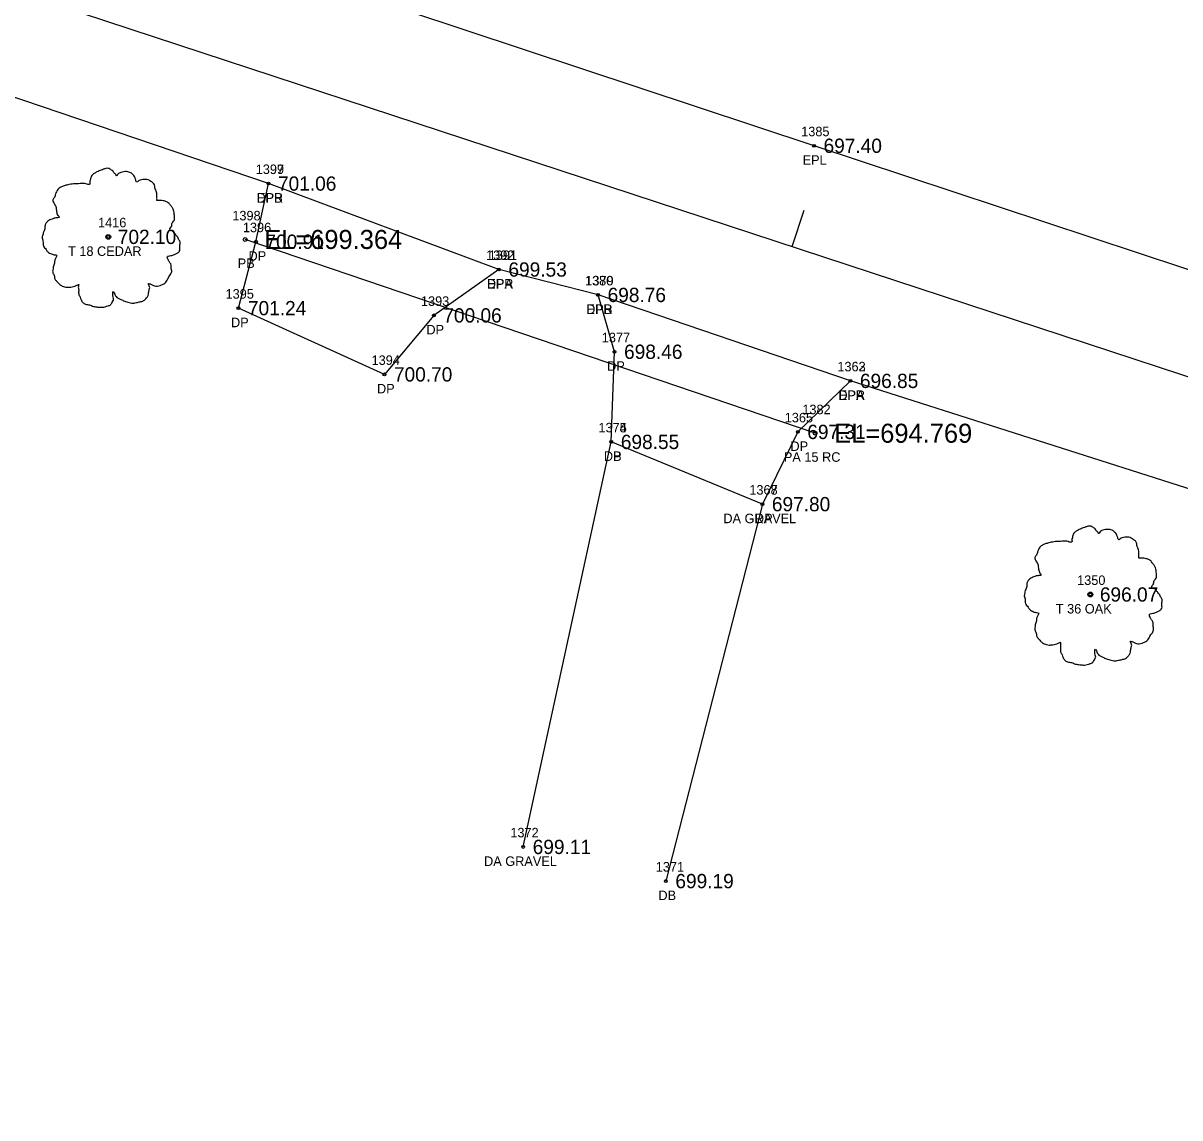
# Model space of a CAD drawing. Extents: x 1655137 to 1657928, y 1003994 to 1005407.
# Drawn here: x 1655718.8 to 1655840.3, y 1004724 to 1004839 of the extents above; entities that cross this region are included whole.
import ezdxf

# ---------------------------------------------------------------- set-up
doc = ezdxf.new("R2010")
doc.units = 0
for name, color, linetype in [('RD_EX_DR_Pipe', 7, 'Continuous'), ('RD_EX_DR_Pipe_txCode', 7, 'Continuous'), ('RD_EX_Driveway', 7, 'Continuous'), ('RD_EX_Driveway_txCode', 7, 'Continuous'), ('RD_EX_Road', 7, 'Continuous'), ('RD_EX_Road_txCode', 7, 'Continuous'), ('RD_EX_TX_Driveway_ELEV', 7, 'Continuous'), ('RD_EX_TX_Road_ELEV', 7, 'Continuous'), ('RD_EX_TX_VEG_ELEV', 7, 'Continuous'), ('RD_EX_VEG', 7, 'Continuous'), ('RD_EX_VEG_txCode', 7, 'Continuous'), ('RD_HC_Cl', 7, 'Continuous'), ('RD_HC_Data_Tic', 7, 'Continuous'), ('RD_SMD_Locator', 7, 'Continuous'), ('RD_TX_Pipe_ElevEX', 7, 'Continuous')]:
    doc.layers.add(name, color=color, linetype=linetype)

msp = doc.modelspace()

# ---------------------------------------------------------------- linework, layer by layer
at = {"layer": 'RD_EX_DR_Pipe'}
msp.add_line((1655802.03, 1004795.9), (1655742.14, 1004816.26), dxfattribs=at)
at = {"layer": 'RD_EX_Driveway'}
for p, q in [((1655771.35, 1004752.44), (1655780.61, 1004794.99)), ((1655796.48, 1004788.45), (1655786.34, 1004748.85))]:
    msp.add_line(p, q, dxfattribs=at)
for points in [[(1655768.8, 1004813.1), (1655761.96, 1004808.28), (1655756.77, 1004802.08), (1655741.43, 1004809.04), (1655743.27, 1004816.02), (1655744.59, 1004822.13)], [(1655805.73, 1004801.4), (1655800.2, 1004796.04), (1655796.48, 1004788.45), (1655780.61, 1004794.99), (1655780.95, 1004804.46), (1655779.22, 1004810.43)]]:
    msp.add_lwpolyline(points, dxfattribs=at)
at = {"layer": 'RD_EX_Road'}
for points in [[(1656365.12, 1004639.99), (1656336.04, 1004649.34), (1656302.55, 1004660.37), (1656279.15, 1004668.23), (1656240.07, 1004681.05), (1656188.23, 1004698.03), (1656166.72, 1004705.51), (1656141.16, 1004714.06), (1656093.11, 1004730.11), (1656044.16, 1004746.75), (1655996.36, 1004762.45), (1655947.2, 1004778.68), (1655899.09, 1004794.03), (1655850.62, 1004809.99), (1655801.91, 1004826.1), (1655753.09, 1004842.31), (1655704.25, 1004858.1)], [(1656358.5, 1004619.83), (1656328.78, 1004629.48), (1656280.77, 1004645.39), (1656247.66, 1004656.11), (1656244.5, 1004656.52), (1656222.03, 1004663.57), (1656217.65, 1004665.96), (1656183.42, 1004677.32), (1656134.59, 1004693.72), (1656086.19, 1004709.75), (1656037.58, 1004726.13), (1655989.57, 1004741.99), (1655940.62, 1004757.88), (1655892.37, 1004773.61), (1655843.48, 1004789.36), (1655805.73, 1004801.4), (1655779.22, 1004810.43), (1655768.8, 1004813.1), (1655744.59, 1004822.13), (1655698.83, 1004837.65)]]:
    msp.add_lwpolyline(points, dxfattribs=at)
at = {"layer": 'RD_EX_VEG'}
for centre, radius in [((1655727.76, 1004816.53), 0.25), ((1655727.75, 1004816.52), 0.0001), ((1655830.94, 1004778.96), 0.25), ((1655830.93, 1004778.94), 0.0001)]:
    msp.add_circle(centre, radius, dxfattribs=at)
for points in [[(1655727.89, 1004823.7), (1655727.59, 1004823.73), (1655727.27, 1004823.63), (1655727.02, 1004823.53), (1655726.79, 1004823.45), (1655726.57, 1004823.35), (1655726.27, 1004823.18), (1655726.04, 1004822.98), (1655725.92, 1004822.73), (1655725.87, 1004822.5), (1655725.82, 1004822.23), (1655725.82, 1004822.05), (1655725.69, 1004822.03), (1655725.54, 1004822.05), (1655725.29, 1004822.13), (1655725.04, 1004822.13), (1655724.8, 1004822.13), (1655724.45, 1004822.1), (1655724.1, 1004822.1), (1655723.82, 1004822.05), (1655723.5, 1004822), (1655723.12, 1004821.88), (1655722.77, 1004821.75), (1655722.47, 1004821.5), (1655722.22, 1004821.03), (1655722.1, 1004820.68), (1655721.95, 1004820.43), (1655722.1, 1004819.98), (1655722.27, 1004819.63), (1655722.3, 1004819.43), (1655722.37, 1004819), (1655722.47, 1004818.78), (1655722.6, 1004818.58), (1655722.52, 1004818.55), (1655722.15, 1004818.5), (1655721.85, 1004818.4), (1655721.42, 1004818.18), (1655721.2, 1004817.95), (1655721.1, 1004817.63), (1655721.07, 1004817.28), (1655720.97, 1004817.08), (1655720.9, 1004816.8), (1655720.87, 1004816.73), (1655720.82, 1004816.4), (1655720.92, 1004815.95), (1655720.95, 1004815.6), (1655721.07, 1004815.38), (1655721.22, 1004815.2), (1655721.4, 1004814.95), (1655721.8, 1004814.73), (1655722.12, 1004814.63), (1655722.32, 1004814.61), (1655722.15, 1004814.11), (1655722.1, 1004813.76), (1655721.97, 1004813.36), (1655721.97, 1004813.28), (1655721.92, 1004812.81), (1655722.07, 1004812.48), (1655722.15, 1004812.11), (1655722.32, 1004811.88), (1655722.6, 1004811.58), (1655722.92, 1004811.36), (1655723.42, 1004811.23), (1655723.82, 1004811.26), (1655724.4, 1004811.43), (1655724.65, 1004811.51), (1655724.62, 1004811.33), (1655724.65, 1004810.96), (1655724.65, 1004810.53), (1655724.8, 1004810.21), (1655724.9, 1004809.93), (1655725.04, 1004809.68), (1655725.37, 1004809.46), (1655725.77, 1004809.38), (1655726.19, 1004809.23), (1655726.64, 1004809.16), (1655727.14, 1004809.13), (1655727.74, 1004809.28), (1655728.02, 1004809.41), (1655728.12, 1004809.58), (1655728.32, 1004809.96), (1655728.27, 1004810.18), (1655728.29, 1004810.78), (1655728.39, 1004810.61), (1655728.57, 1004810.26), (1655729.07, 1004809.96), (1655729.47, 1004809.78), (1655729.94, 1004809.63), (1655730.24, 1004809.56), (1655730.72, 1004809.63), (1655731.09, 1004809.71), (1655731.47, 1004809.83), (1655731.77, 1004810.11), (1655731.94, 1004810.38), (1655731.99, 1004810.66), (1655732.07, 1004811.03), (1655732.12, 1004811.21)], [(1655732.12, 1004811.21), (1655732.04, 1004811.38), (1655731.99, 1004811.63), (1655732.07, 1004811.61), (1655732.24, 1004811.56), (1655732.52, 1004811.43), (1655732.74, 1004811.36), (1655733.07, 1004811.38), (1655733.34, 1004811.48), (1655733.79, 1004811.76), (1655734.07, 1004812.23), (1655734.34, 1004812.63), (1655734.42, 1004812.96), (1655734.37, 1004813.18), (1655734.34, 1004813.68), (1655734.14, 1004813.93), (1655734.09, 1004814.06), (1655733.99, 1004814.46), (1655734.07, 1004814.51), (1655734.34, 1004814.56), (1655734.72, 1004814.68), (1655734.99, 1004814.8), (1655735.22, 1004814.98), (1655735.29, 1004815.2), (1655735.27, 1004815.6), (1655735.32, 1004816), (1655735.24, 1004816.15), (1655735.14, 1004816.3), (1655735.07, 1004816.5), (1655734.92, 1004816.65), (1655734.82, 1004816.8), (1655734.72, 1004816.9), (1655734.59, 1004817.05), (1655734.42, 1004817.18), (1655734.27, 1004817.23), (1655734.22, 1004817.38), (1655734.37, 1004817.58), (1655734.42, 1004817.68), (1655734.44, 1004817.9), (1655734.67, 1004818.25), (1655734.72, 1004818.65), (1655734.67, 1004819.08), (1655734.62, 1004819.35), (1655734.47, 1004819.63), (1655734.27, 1004819.88), (1655734.14, 1004820.05), (1655733.97, 1004820.18), (1655733.64, 1004820.3), (1655733.39, 1004820.35), (1655733.04, 1004820.35), (1655732.84, 1004820.4), (1655732.87, 1004820.45), (1655732.87, 1004820.6), (1655732.87, 1004820.88), (1655732.79, 1004821.33), (1655732.64, 1004821.83), (1655732.64, 1004821.85), (1655732.54, 1004822.1), (1655732.32, 1004822.3), (1655732.14, 1004822.4), (1655731.94, 1004822.53), (1655731.69, 1004822.55), (1655731.39, 1004822.55), (1655731.12, 1004822.5), (1655730.92, 1004822.4), (1655730.74, 1004822.28), (1655730.67, 1004822.43), (1655730.57, 1004822.73), (1655730.52, 1004822.88), (1655730.37, 1004823.05), (1655730.14, 1004823.25), (1655729.69, 1004823.38), (1655729.07, 1004823.3), (1655728.77, 1004823.1), (1655728.62, 1004822.93), (1655728.57, 1004823.05), (1655728.37, 1004823.25), (1655728.27, 1004823.43), (1655728.09, 1004823.55), (1655727.94, 1004823.65), (1655727.84, 1004823.7)], [(1655831.07, 1004786.12), (1655830.77, 1004786.15), (1655830.45, 1004786.05), (1655830.2, 1004785.95), (1655829.97, 1004785.87), (1655829.75, 1004785.77), (1655829.45, 1004785.6), (1655829.22, 1004785.4), (1655829.1, 1004785.15), (1655829.05, 1004784.92), (1655829, 1004784.65), (1655829, 1004784.47), (1655828.87, 1004784.45), (1655828.72, 1004784.47), (1655828.47, 1004784.55), (1655828.22, 1004784.55), (1655827.97, 1004784.55), (1655827.62, 1004784.52), (1655827.27, 1004784.52), (1655827, 1004784.47), (1655826.67, 1004784.42), (1655826.3, 1004784.3), (1655825.95, 1004784.17), (1655825.65, 1004783.92), (1655825.4, 1004783.45), (1655825.27, 1004783.1), (1655825.12, 1004782.85), (1655825.27, 1004782.4), (1655825.45, 1004782.05), (1655825.47, 1004781.85), (1655825.55, 1004781.42), (1655825.65, 1004781.2), (1655825.77, 1004781), (1655825.7, 1004780.97), (1655825.32, 1004780.92), (1655825.02, 1004780.82), (1655824.6, 1004780.6), (1655824.37, 1004780.37), (1655824.27, 1004780.05), (1655824.25, 1004779.7), (1655824.15, 1004779.5), (1655824.07, 1004779.23), (1655824.05, 1004779.15), (1655824, 1004778.83), (1655824.1, 1004778.38), (1655824.12, 1004778.03), (1655824.25, 1004777.8), (1655824.4, 1004777.63), (1655824.57, 1004777.38), (1655824.97, 1004777.15), (1655825.3, 1004777.05), (1655825.5, 1004777.03), (1655825.32, 1004776.53), (1655825.27, 1004776.18), (1655825.15, 1004775.78), (1655825.15, 1004775.7), (1655825.1, 1004775.23), (1655825.25, 1004774.9), (1655825.32, 1004774.53), (1655825.5, 1004774.3), (1655825.77, 1004774), (1655826.1, 1004773.78), (1655826.6, 1004773.65), (1655827, 1004773.68), (1655827.57, 1004773.85), (1655827.82, 1004773.93), (1655827.8, 1004773.75), (1655827.82, 1004773.38), (1655827.82, 1004772.95), (1655827.97, 1004772.63), (1655828.07, 1004772.35), (1655828.22, 1004772.1), (1655828.55, 1004771.88), (1655828.95, 1004771.8), (1655829.37, 1004771.65), (1655829.82, 1004771.58), (1655830.32, 1004771.55), (1655830.92, 1004771.7), (1655831.2, 1004771.83), (1655831.3, 1004772), (1655831.5, 1004772.38), (1655831.45, 1004772.6), (1655831.47, 1004773.2), (1655831.57, 1004773.03), (1655831.75, 1004772.68), (1655832.24, 1004772.38), (1655832.64, 1004772.2), (1655833.12, 1004772.05), (1655833.42, 1004771.98), (1655833.89, 1004772.05), (1655834.27, 1004772.13), (1655834.64, 1004772.25), (1655834.94, 1004772.53), (1655835.12, 1004772.8), (1655835.17, 1004773.08), (1655835.24, 1004773.45), (1655835.29, 1004773.63)], [(1655835.29, 1004773.63), (1655835.22, 1004773.8), (1655835.17, 1004774.05), (1655835.24, 1004774.03), (1655835.42, 1004773.98), (1655835.69, 1004773.85), (1655835.92, 1004773.78), (1655836.24, 1004773.8), (1655836.52, 1004773.9), (1655836.97, 1004774.18), (1655837.24, 1004774.65), (1655837.52, 1004775.05), (1655837.59, 1004775.38), (1655837.54, 1004775.6), (1655837.52, 1004776.1), (1655837.32, 1004776.35), (1655837.27, 1004776.48), (1655837.17, 1004776.88), (1655837.24, 1004776.93), (1655837.52, 1004776.98), (1655837.89, 1004777.1), (1655838.17, 1004777.23), (1655838.39, 1004777.4), (1655838.47, 1004777.63), (1655838.44, 1004778.03), (1655838.49, 1004778.43), (1655838.42, 1004778.58), (1655838.32, 1004778.73), (1655838.24, 1004778.93), (1655838.09, 1004779.08), (1655837.99, 1004779.23), (1655837.89, 1004779.33), (1655837.77, 1004779.48), (1655837.59, 1004779.6), (1655837.44, 1004779.65), (1655837.39, 1004779.8), (1655837.54, 1004780), (1655837.59, 1004780.1), (1655837.62, 1004780.32), (1655837.84, 1004780.67), (1655837.89, 1004781.07), (1655837.84, 1004781.5), (1655837.79, 1004781.77), (1655837.64, 1004782.05), (1655837.44, 1004782.3), (1655837.32, 1004782.47), (1655837.14, 1004782.6), (1655836.82, 1004782.72), (1655836.57, 1004782.77), (1655836.22, 1004782.77), (1655836.02, 1004782.82), (1655836.04, 1004782.87), (1655836.04, 1004783.02), (1655836.04, 1004783.3), (1655835.97, 1004783.75), (1655835.82, 1004784.25), (1655835.82, 1004784.27), (1655835.72, 1004784.52), (1655835.49, 1004784.72), (1655835.32, 1004784.82), (1655835.12, 1004784.95), (1655834.87, 1004784.97), (1655834.57, 1004784.97), (1655834.29, 1004784.92), (1655834.09, 1004784.82), (1655833.92, 1004784.7), (1655833.84, 1004784.85), (1655833.74, 1004785.15), (1655833.69, 1004785.3), (1655833.54, 1004785.47), (1655833.32, 1004785.67), (1655832.87, 1004785.8), (1655832.24, 1004785.72), (1655831.94, 1004785.52), (1655831.79, 1004785.35), (1655831.75, 1004785.47), (1655831.55, 1004785.67), (1655831.45, 1004785.85), (1655831.27, 1004785.97), (1655831.12, 1004786.07), (1655831.02, 1004786.12)]]:
    msp.add_spline(points, degree=3, dxfattribs=at)
at = {"layer": 'RD_HC_Cl'}
msp.add_line((1655701.51, 1004847.78), (1656069.26, 1004726.84), dxfattribs=at)
at = {"layer": 'RD_HC_Data_Tic'}
msp.add_line((1655799.61, 1004815.52), (1655800.86, 1004819.32), dxfattribs=at)
at = {"layer": 'RD_SMD_Locator'}
for centre, radius in [((1655801.91, 1004826.1), 0.15), ((1655744.59, 1004822.13), 0.15), ((1655744.59, 1004822.13), 0.15), ((1655727.76, 1004816.53), 0.15), ((1655742.14, 1004816.26), 0.2), ((1655743.27, 1004816.02), 0.15), ((1655768.8, 1004813.1), 0.15), ((1655768.8, 1004813.1), 0.15), ((1655779.22, 1004810.43), 0.15), ((1655779.22, 1004810.43), 0.15), ((1655741.43, 1004809.04), 0.15), ((1655761.96, 1004808.28), 0.15), ((1655780.95, 1004804.46), 0.15), ((1655756.77, 1004802.08), 0.15), ((1655805.73, 1004801.4), 0.15), ((1655805.73, 1004801.4), 0.15), ((1655800.2, 1004796.04), 0.15), ((1655802.03, 1004795.9), 0.2), ((1655780.61, 1004794.99), 0.15), ((1655780.61, 1004794.99), 0.15), ((1655796.48, 1004788.45), 0.15), ((1655796.48, 1004788.45), 0.15), ((1655830.94, 1004778.96), 0.15), ((1655771.35, 1004752.44), 0.15), ((1655786.34, 1004748.85), 0.15)]:
    msp.add_circle(centre, radius, dxfattribs=at)

# ---------------------------------------------------------------- texts
at = {"layer": 'RD_EX_DR_Pipe_txCode'}
for s, p in [('1398', (1655740.79, 1004818.26)), ('PB', (1655741.36, 1004813.26)), ('1382', (1655800.68, 1004797.9)), ('PA 15 RC', (1655798.74, 1004792.9))]:
    msp.add_text(s, height=1, dxfattribs=at).set_placement(p)
at = {"layer": 'RD_EX_Driveway_txCode'}
for s, p in [('1397', (1655743.25, 1004823.13)), ('DPB', (1655743.34, 1004820.13)), ('1396', (1655741.9, 1004817.02)), ('DP', (1655742.49, 1004814.02)), ('1392', (1655767.45, 1004814.1)), ('1379', (1655777.88, 1004811.43)), ('DPA', (1655767.53, 1004811.1)), ('1395', (1655740.08, 1004810.04)), ('1393', (1655760.61, 1004809.28)), ('DPB', (1655777.97, 1004808.43)), ('DP', (1655740.65, 1004807.04)), ('DP', (1655761.18, 1004806.28)), ('1377', (1655779.61, 1004805.46)), ('1394', (1655755.42, 1004803.08)), ('DP', (1655780.17, 1004802.46)), ('1363', (1655804.36, 1004802.4)), ('DP', (1655755.99, 1004800.08)), ('DPA', (1655804.47, 1004799.4)), ('1365', (1655798.83, 1004797.04)), ('1374', (1655779.26, 1004795.99)), ('1375', (1655779.26, 1004795.99)), ('DP', (1655799.43, 1004794.04)), ('DB', (1655779.83, 1004792.99)), ('DP', (1655779.83, 1004792.99)), ('1367', (1655795.11, 1004789.45)), ('1368', (1655795.11, 1004789.45)), ('DA GRAVEL', (1655792.38, 1004786.45)), ('DP', (1655795.7, 1004786.45)), ('1372', (1655770, 1004753.44)), ('DA GRAVEL', (1655767.24, 1004750.44)), ('1371', (1655785.28, 1004749.85)), ('DB', (1655785.56, 1004746.85))]:
    msp.add_text(s, height=1, dxfattribs=at).set_placement(p)
at = {"layer": 'RD_EX_Road_txCode'}
for s, p in [('1385', (1655800.56, 1004827.1)), ('EPL', (1655800.71, 1004824.1)), ('1399', (1655743.25, 1004823.13)), ('EPR', (1655743.37, 1004820.13)), ('1391', (1655767.73, 1004814.1)), ('1380', (1655777.84, 1004811.43)), ('EPR', (1655767.57, 1004811.1)), ('EPR', (1655777.99, 1004808.43)), ('1362', (1655804.36, 1004802.4)), ('EPR', (1655804.51, 1004799.4))]:
    msp.add_text(s, height=1, dxfattribs=at).set_placement(p)
at = {"layer": 'RD_EX_TX_Driveway_ELEV'}
for s, p in [('701.06', (1655745.59, 1004821.38)), ('700.91', (1655744.27, 1004815.27)), ('699.53', (1655769.8, 1004812.35)), ('698.76', (1655780.22, 1004809.68)), ('701.24', (1655742.43, 1004808.29)), ('700.06', (1655762.96, 1004807.53)), ('698.46', (1655781.95, 1004803.71)), ('700.70', (1655757.77, 1004801.33)), ('696.85', (1655806.73, 1004800.65)), ('697.31', (1655801.2, 1004795.29)), ('698.55', (1655781.61, 1004794.24)), ('698.55', (1655781.61, 1004794.24)), ('697.80', (1655797.48, 1004787.7)), ('697.80', (1655797.48, 1004787.7)), ('699.11', (1655772.35, 1004751.69)), ('699.19', (1655787.34, 1004748.1))]:
    msp.add_text(s, height=1.5, dxfattribs=at).set_placement(p)
at = {"layer": 'RD_EX_TX_Road_ELEV'}
for s, p in [('697.40', (1655802.91, 1004825.35)), ('701.06', (1655745.59, 1004821.38)), ('699.53', (1655769.8, 1004812.35)), ('698.76', (1655780.22, 1004809.68)), ('696.85', (1655806.73, 1004800.65))]:
    msp.add_text(s, height=1.5, dxfattribs=at).set_placement(p)
at = {"layer": 'RD_EX_TX_VEG_ELEV'}
for s, p in [('702.10', (1655728.76, 1004815.78)), ('696.07', (1655831.94, 1004778.21))]:
    msp.add_text(s, height=1.5, dxfattribs=at).set_placement(p)
at = {"layer": 'RD_EX_VEG_txCode'}
for s, p in [('1416', (1655726.68, 1004817.53)), ('T 18 CEDAR', (1655723.53, 1004814.53)), ('1350', (1655829.55, 1004779.96)), ('T 36 OAK', (1655827.31, 1004776.96))]:
    msp.add_text(s, height=1, dxfattribs=at).set_placement(p)
at = {"layer": 'RD_TX_Pipe_ElevEX'}
for s, p in [('EL=699.364', (1655744.14, 1004815.26)), ('EL=694.769', (1655804.03, 1004794.9))]:
    msp.add_text(s, height=2, dxfattribs=at).set_placement(p)

doc.saveas('drawing.dxf')
